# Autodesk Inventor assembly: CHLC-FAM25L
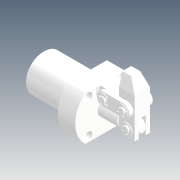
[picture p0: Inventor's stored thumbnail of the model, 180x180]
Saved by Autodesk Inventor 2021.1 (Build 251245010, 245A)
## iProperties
Created: 2019-04
Part Number: CHLC-FAM25L
Description: STEP AP214
Document SubType Name: Assembly
Designer: user
Title: CHLC-FAM25L.STEP
Revision Number: ÈÎºÎ
Sending System: SolidWorks 2016
Preprocessor: SwSTEP 2.0
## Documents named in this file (10)
- D:\Vault_2016\Projekty\Clamptek\Hydraulic\CHLC\CHLC-25\Inventor\CHLC-FAM25L\CHLC-FAM25L.iam
- D:\Vault_2016\Projekty\Clamptek\Hydraulic\CHLC\CHLC-25\Inventor\CHLC-FAM25L\CHLC-FAM25BT.ipt
- D:\Vault_2016\Projekty\Clamptek\Hydraulic\CHLC\CHLC-25\Inventor\CHLC-FAM25L\CHLC-25CX.ipt
- D:\Vault_2016\Projekty\Clamptek\Hydraulic\CHLC\CHLC-25\Inventor\CHLC-FAM25L\CHLC-25DX.ipt
- D:\Vault_2016\Projekty\Clamptek\Hydraulic\CHLC\CHLC-25\Inventor\CHLC-FAM25L\CHLC-25HSG.ipt
- D:\Vault_2016\Projekty\Clamptek\Hydraulic\CHLC\CHLC-25\Inventor\CHLC-FAM25L\CHLC-25KKDC.ipt
- D:\Vault_2016\Projekty\Clamptek\Hydraulic\CHLC\CHLC-25\Inventor\CHLC-FAM25L\CHLC-25LG.ipt
- D:\Vault_2016\Projekty\Clamptek\Hydraulic\CHLC\CHLC-25\Inventor\CHLC-FAM25L\CHLC-25ZC-HAN.ipt
- D:\Vault_2016\Projekty\Clamptek\Hydraulic\CHLC\CHLC-25\Inventor\CHLC-FAM25L\CHLC-25ZC.ipt
- D:\Vault_2016\Projekty\Clamptek\Hydraulic\CHLC\CHLC-25\Inventor\CHLC-FAM25L\Ñ¹±Û.ipt
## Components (16 placed, 16 different names)
1. CHLC-FAM25BT_1
2. CHLC-25CX_2
3. CHLC-25DX_3
4. CHLC-25HSG_4
5. CHLC-25KKDC_5
6. CHLC-25LG_6
7. CHLC-25ZC-HAN_7
8. CHLC-25ZC_8
9. CHLC-25LG_9
10. CHLC-25KKDC_10
11. CHLC-25KKDC_11
12. CHLC-25KKDC_12
13. CHLC-25KKDC_13
14. CHLC-25KKDC_14
15. CHLC-25CX_15
16. Ñ¹±Û_16
